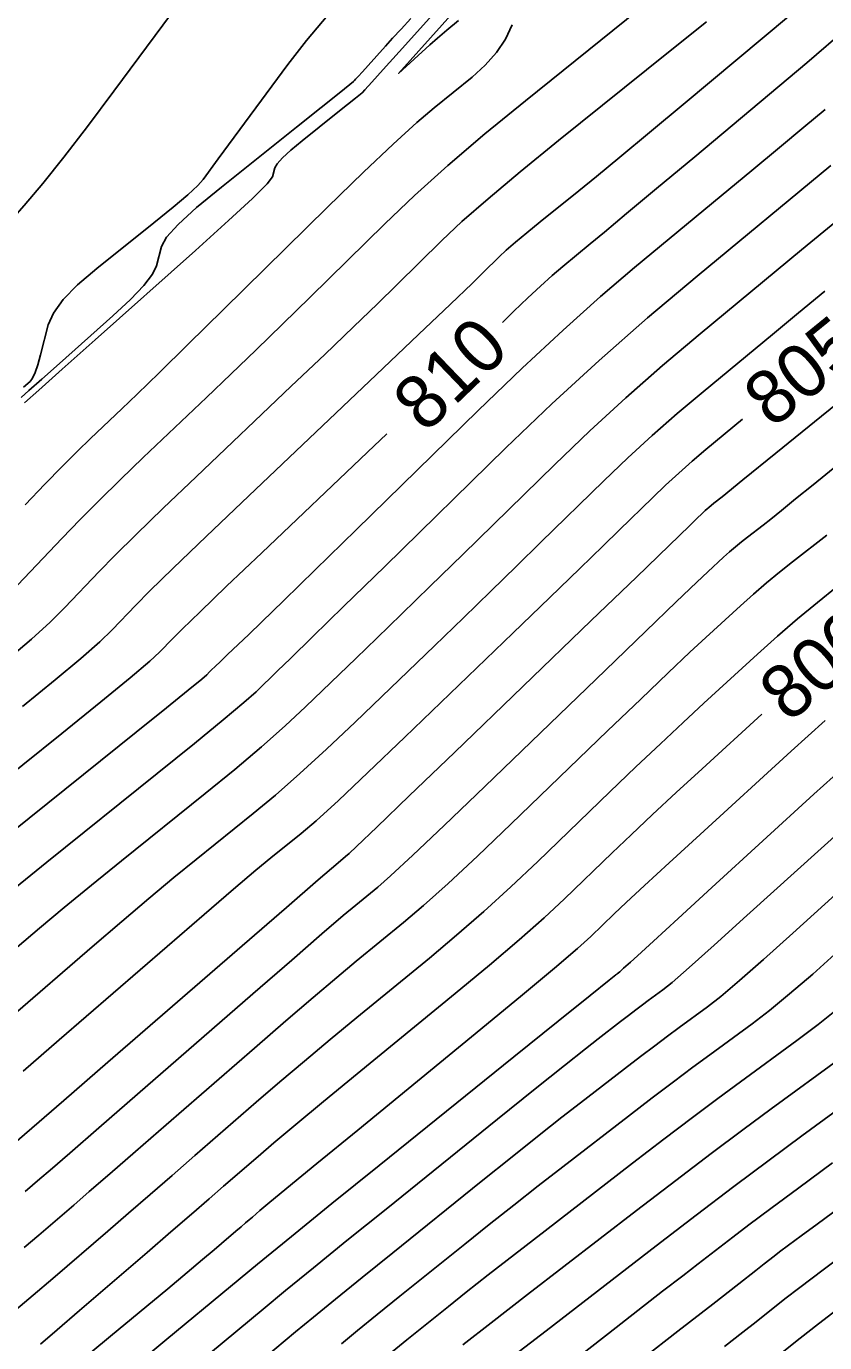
# Model space of a CAD drawing. Extents: x 2079879 to 2092887, y 778083 to 784051.
# Drawn here: x 2084061.2 to 2084103, y 780863.7 to 780932.5 of the extents above; entities that cross this region are included whole.
import ezdxf

# ---------------------------------------------------------------- set-up
doc = ezdxf.new("R2010")
doc.units = 0
doc.layers.add('DT_X_Contour_Major', color=7, linetype='Continuous')
doc.layers.add('DT_X_Contour_Minor', color=7, linetype='Continuous')

msp = doc.modelspace()

# ---------------------------------------------------------------- linework, layer by layer
at = {"layer": 'DT_X_Contour_Major'}
for points in [[(2084083.224, 780934.036), (2084080.694, 780931.221), (2084079.863, 780930.296), (2084079.268, 780929.633), (2084078.907, 780929.232), (2084078.782, 780929.094), (2084078.762, 780929.072), (2084078.671, 780928.998), (2084078.415, 780928.793), (2084077.992, 780928.455), (2084077.404, 780927.986), (2084075.614, 780926.559), (2084075.021, 780926.069), (2084074.586, 780925.67), (2084074.307, 780925.361), (2084074.185, 780925.144), (2084074.068, 780924.685), (2084073.784, 780924.315), (2084073.019, 780923.551), (2084071.772, 780922.392), (2084070.045, 780920.838), (2084064.797, 780916.168), (2084063.073, 780914.634), (2084061.837, 780913.535), (2084061.089, 780912.87)], [(2084104.171, 780932.492), (2084102.031, 780930.64), (2084096.158, 780925.736), (2084094.165, 780924.072), (2084092.588, 780922.757), (2084091.43, 780921.792), (2084090.688, 780921.177), (2084089.266, 780920.002), (2084088.706, 780919.525), (2084088.091, 780918.974), (2084087.421, 780918.35), (2084086.697, 780917.652), (2084086.101, 780917.07)], [(2084098.661, 780912.005), (2084096.748, 780910.424), (2084096.027, 780909.816), (2084095.324, 780909.197), (2084094.637, 780908.567), (2084093.967, 780907.927), (2084092.204, 780906.204), (2084091.361, 780905.384), (2084090.153, 780904.214), (2084088.58, 780902.696), (2084086.643, 780900.828), (2084080.991, 780895.382), (2084079.062, 780893.536), (2084077.515, 780892.081), (2084076.349, 780891.017), (2084075.565, 780890.346), (2084073.983, 780889.076), (2084073.199, 780888.43), (2084072.034, 780887.445), (2084070.487, 780886.12), (2084068.558, 780884.455), (2084062.906, 780879.563), (2084061.017, 780877.921)], [(2084080.05, 780911.243), (2084079.044, 780910.286), (2084073.516, 780905.034), (2084071.669, 780903.276), (2084070.277, 780901.943), (2084069.338, 780901.035), (2084068.852, 780900.551), (2084068.163, 780899.826), (2084067.649, 780899.357), (2084066.625, 780898.495), (2084065.09, 780897.24), (2084063.045, 780895.59), (2084056.91, 780890.667)], [(2084099.664, 780896.596), (2084096.539, 780893.736), (2084095.183, 780892.489), (2084093.946, 780891.341), (2084092.83, 780890.291), (2084091.834, 780889.34), (2084089.338, 780886.935), (2084088.279, 780885.949), (2084086.974, 780884.796), (2084085.422, 780883.475), (2084083.625, 780881.986), (2084078.503, 780877.792), (2084076.737, 780876.342), (2084075.284, 780875.139), (2084074.142, 780874.183), (2084073.312, 780873.474), (2084071.513, 780871.91), (2084070.757, 780871.255), (2084069.838, 780870.461), (2084068.756, 780869.528), (2084067.511, 780868.456), (2084063.974, 780865.414), (2084062.801, 780864.405), (2084061.933, 780863.66)], [(2084103.684, 780884.216), (2084102.33, 780883.007), (2084101.125, 780881.971), (2084100.07, 780881.105), (2084099.163, 780880.411), (2084096.944, 780878.789), (2084096.054, 780878.132), (2084095.05, 780877.379), (2084093.932, 780876.53), (2084092.7, 780875.584), (2084089.261, 780872.933), (2084087.973, 780871.935), (2084086.689, 780870.929), (2084085.409, 780869.915), (2084084.133, 780868.894), (2084080.735, 780866.16), (2084079.545, 780865.201), (2084078.524, 780864.374), (2084077.671, 780863.678)], [(2084105.037, 780871.756), (2084102.559, 780869.94), (2084101.721, 780869.325), (2084101.066, 780868.841), (2084100.595, 780868.488), (2084100.307, 780868.266), (2084099.784, 780867.849), (2084099.355, 780867.511), (2084098.46, 780866.813), (2084097.099, 780865.752), (2084095.273, 780864.33), (2084089.781, 780860.056), (2084087.717, 780858.447), (2084087.46, 780858.246)]]:
    msp.add_lwpolyline(points, dxfattribs=at)
at = {"layer": 'DT_X_Contour_Minor'}
for points in [[(2084086.912, 780937.046), (2084080.662, 780930.09), (2084082.293, 780931.578), (2084082.693, 780931.932), (2084083.195, 780932.356), (2084083.799, 780932.851)], [(2084069.632, 780934.388), (2084065.777, 780929.156), (2084064.399, 780927.312), (2084063.157, 780925.703), (2084062.051, 780924.328), (2084061.081, 780923.189), (2084058.675, 780920.464), (2084057.831, 780919.495), (2084057.106, 780918.631), (2084056.498, 780917.873), (2084056.009, 780917.22), (2084054.86, 780915.618), (2084054.221, 780914.817), (2084053.164, 780913.616), (2084051.69, 780912.016), (2084049.799, 780910.015), (2084044.2, 780904.145), (2084042.347, 780902.199), (2084040.988, 780900.762), (2084040.122, 780899.834), (2084039.75, 780899.415), (2084039.166, 780898.65), (2084027.781, 780889.557), (2084025.603, 780887.819)], [(2084093.215, 780933.405), (2084087.304, 780928.661), (2084085.182, 780926.925), (2084083.247, 780925.273), (2084081.501, 780923.707), (2084079.942, 780922.225), (2084076.036, 780918.388), (2084074.599, 780916.981), (2084073.218, 780915.639), (2084071.892, 780914.362), (2084070.621, 780913.149), (2084067.308, 780910.001), (2084066.111, 780908.852), (2084065.005, 780907.768), (2084063.99, 780906.749), (2084063.067, 780905.793), (2084060.725, 780903.332)], [(2084077.246, 780933.463), (2084075.851, 780931.816), (2084074.866, 780930.562), (2084071.23, 780925.628), (2084070.447, 780924.54), (2084070.16, 780924.224), (2084069.634, 780923.743), (2084068.87, 780923.096), (2084067.867, 780922.284), (2084064.874, 780919.898), (2084063.874, 780919.042), (2084063.117, 780918.264), (2084062.604, 780917.563), (2084062.334, 780916.941), (2084061.94, 780915.384), (2084061.794, 780914.858), (2084061.653, 780914.45), (2084061.516, 780914.159), (2084061.385, 780913.985), (2084061.039, 780913.678)], [(2084096.769, 780932.786), (2084094.791, 780931.196), (2084089.032, 780926.574), (2084087.031, 780924.948), (2084085.348, 780923.537), (2084083.983, 780922.341), (2084082.935, 780921.361), (2084080.566, 780919.033), (2084079.555, 780918.048), (2084078.299, 780916.837), (2084076.799, 780915.4), (2084075.054, 780913.739), (2084070.074, 780909.007), (2084068.355, 780907.366), (2084066.936, 780905.992), (2084065.816, 780904.885), (2084064.995, 780904.046), (2084063.204, 780902.163), (2084062.434, 780901.399), (2084061.465, 780900.517), (2084060.3, 780899.519)], [(2084081.312, 780932.954), (2084080.794, 780932.406), (2084080.348, 780931.926), (2084079.973, 780931.514), (2084079.068, 780930.507), (2084078.769, 780930.174), (2084078.551, 780929.931), (2084078.413, 780929.779), (2084078.356, 780929.716), (2084078.311, 780929.67), (2084078.112, 780929.507), (2084077.549, 780929.056), (2084076.622, 780928.315), (2084075.33, 780927.284), (2084071.399, 780924.149), (2084070.097, 780923.073), (2084069.14, 780922.197), (2084068.528, 780921.52), (2084068.259, 780921.042), (2084068.004, 780920.034), (2084067.789, 780919.587), (2084067.336, 780919.001), (2084066.644, 780918.276), (2084065.715, 780917.412), (2084062.918, 780914.923), (2084061.996, 780914.103), (2084061.328, 780913.509), (2084060.914, 780913.142)], [(2084101.066, 780933.066), (2084095.665, 780928.555), (2084093.798, 780926.999), (2084092.247, 780925.713), (2084091.013, 780924.698), (2084090.096, 780923.953), (2084088.071, 780922.329), (2084087.368, 780921.757), (2084086.777, 780921.261), (2084086.297, 780920.841), (2084085.929, 780920.497), (2084085.096, 780919.678), (2084084.511, 780919.114), (2084083.381, 780918.034), (2084081.706, 780916.439), (2084079.486, 780914.328), (2084072.839, 780908.013), (2084070.6, 780905.879), (2084068.868, 780904.216), (2084067.642, 780903.022), (2084066.924, 780902.298), (2084065.683, 780900.995), (2084065.041, 780900.378), (2084064.045, 780899.506), (2084062.695, 780898.379), (2084060.99, 780896.997)], [(2084086.611, 780932.627), (2084086.251, 780931.88), (2084085.781, 780931.175), (2084085.201, 780930.513), (2084084.51, 780929.893), (2084082.522, 780928.297), (2084081.614, 780927.522), (2084080.383, 780926.396), (2084078.828, 780924.919), (2084076.948, 780923.09), (2084071.506, 780917.743), (2084069.643, 780915.915), (2084068.136, 780914.442), (2084066.985, 780913.324), (2084066.189, 780912.559), (2084064.542, 780910.995), (2084063.866, 780910.339), (2084063.074, 780909.545), (2084062.164, 780908.612), (2084061.138, 780907.541)], [(2084102.977, 780928.2), (2084101.87, 780927.277), (2084100.594, 780926.217), (2084099.15, 780925.02), (2084097.537, 780923.686), (2084093.012, 780919.946), (2084091.228, 780918.426), (2084089.27, 780916.673), (2084087.138, 780914.686), (2084084.833, 780912.465), (2084078.452, 780906.231), (2084076.306, 780904.136), (2084074.654, 780902.526), (2084073.496, 780901.402), (2084072.832, 780900.763), (2084071.72, 780899.706), (2084071.348, 780899.352), (2084071.068, 780899.084), (2084070.879, 780898.901), (2084070.781, 780898.803), (2084070.642, 780898.657), (2084070.371, 780898.429), (2084069.663, 780897.852), (2084068.516, 780896.927), (2084066.932, 780895.654), (2084060.442, 780890.447)], [(2084103.28, 780925.281), (2084096.283, 780919.497), (2084093.69, 780917.309), (2084091.159, 780915.083), (2084088.689, 780912.817), (2084086.28, 780910.513), (2084079.938, 780904.317), (2084077.804, 780902.233), (2084076.159, 780900.628), (2084075.003, 780899.502), (2084074.336, 780898.855), (2084073.208, 780897.768), (2084072.567, 780897.195), (2084071.492, 780896.289), (2084069.982, 780895.051), (2084068.037, 780893.482), (2084062.27, 780888.854), (2084060.306, 780887.273)], [(2084103.587, 780922.381), (2084101.751, 780920.864), (2084096.438, 780916.473), (2084094.469, 780914.812), (2084092.547, 780913.121), (2084090.671, 780911.4), (2084088.842, 780909.651), (2084084.027, 780904.946), (2084082.323, 780903.283), (2084080.824, 780901.824), (2084079.529, 780900.567), (2084078.438, 780899.513), (2084075.802, 780896.973), (2084074.732, 780895.975), (2084073.499, 780894.886), (2084072.104, 780893.707), (2084070.546, 780892.437), (2084066.174, 780888.928), (2084064.603, 780887.659), (2084063.17, 780886.483), (2084061.873, 780885.399), (2084060.714, 780884.408)], [(2084102.964, 780918.702), (2084101.588, 780917.574), (2084100.222, 780916.448), (2084096.593, 780913.449), (2084095.248, 780912.314), (2084093.935, 780911.159), (2084092.654, 780909.984), (2084091.405, 780908.789), (2084088.116, 780905.575), (2084086.842, 780904.334), (2084085.488, 780903.019), (2084084.055, 780901.631), (2084082.541, 780900.17), (2084078.396, 780896.177), (2084076.897, 780894.755), (2084075.507, 780893.484), (2084074.227, 780892.362), (2084073.056, 780891.391), (2084070.079, 780889.002), (2084068.901, 780888.045), (2084067.602, 780886.964), (2084066.18, 780885.759), (2084064.636, 780884.432), (2084060.356, 780880.727)], [(2084110.041, 780918.034), (2084102.795, 780912.173), (2084100.405, 780910.24), (2084098.67, 780908.836), (2084097.589, 780907.961), (2084097.164, 780907.616), (2084096.903, 780907.4), (2084096.806, 780907.318), (2084096.712, 780907.235), (2084096.62, 780907.151), (2084096.53, 780907.065), (2084096.293, 780906.833), (2084095.88, 780906.434), (2084094.818, 780905.41), (2084093.106, 780903.76), (2084090.746, 780901.486), (2084083.585, 780894.587), (2084081.227, 780892.316), (2084079.522, 780890.678), (2084078.472, 780889.673), (2084078.075, 780889.3), (2084077.888, 780889.15), (2084077.497, 780888.816), (2084076.466, 780887.926), (2084074.793, 780886.48), (2084072.48, 780884.478), (2084065.457, 780878.4), (2084063.145, 780876.397), (2084061.477, 780874.949), (2084060.453, 780874.054)], [(2084104.997, 780910.74), (2084102.347, 780908.58), (2084101.438, 780907.841), (2084100.701, 780907.245), (2084100.135, 780906.791), (2084099.74, 780906.48), (2084098.914, 780905.84), (2084098.604, 780905.595), (2084098.294, 780905.338), (2084097.983, 780905.07), (2084097.672, 780904.791), (2084096.842, 780904.031), (2084096.273, 780903.497), (2084095.191, 780902.464), (2084093.595, 780900.931), (2084091.485, 780898.9), (2084085.173, 780892.819), (2084083.048, 780890.779), (2084081.408, 780889.222), (2084080.251, 780888.146), (2084079.579, 780887.553), (2084078.431, 780886.613), (2084077.772, 780886.059), (2084076.654, 780885.101), (2084075.077, 780883.739), (2084073.042, 780881.973), (2084067.004, 780876.726), (2084064.986, 780874.973), (2084063.462, 780873.65), (2084062.433, 780872.757), (2084061.897, 780872.293), (2084061.126, 780871.631)], [(2084103.068, 780905.946), (2084101.265, 780904.55), (2084100.589, 780904.014), (2084099.911, 780903.454), (2084099.233, 780902.868), (2084098.554, 780902.259), (2084096.741, 780900.6), (2084095.91, 780899.828), (2084094.776, 780898.756), (2084093.34, 780897.384), (2084091.601, 780895.713), (2084086.562, 780890.857), (2084084.792, 780889.169), (2084083.263, 780887.746), (2084081.975, 780886.589), (2084080.928, 780885.697), (2084078.455, 780883.673), (2084077.427, 780882.82), (2084076.197, 780881.781), (2084074.765, 780880.554), (2084073.132, 780879.14), (2084068.507, 780875.121), (2084066.903, 780873.729), (2084065.563, 780872.566), (2084064.486, 780871.634), (2084063.671, 780870.931), (2084061.85, 780869.364), (2084061.083, 780868.712)], [(2084103.617, 780903.259), (2084102.574, 780902.433), (2084101.529, 780901.569), (2084100.483, 780900.666), (2084099.435, 780899.726), (2084096.64, 780897.168), (2084095.546, 780896.158), (2084094.361, 780895.048), (2084093.085, 780893.838), (2084091.718, 780892.526), (2084087.95, 780888.896), (2084086.536, 780887.559), (2084085.119, 780886.271), (2084083.699, 780885.032), (2084082.276, 780883.842), (2084078.479, 780880.732), (2084077.082, 780879.581), (2084075.741, 780878.46), (2084074.454, 780877.369), (2084073.222, 780876.307), (2084070.01, 780873.516), (2084068.821, 780872.484), (2084067.664, 780871.482), (2084066.539, 780870.511), (2084065.446, 780869.569), (2084062.574, 780867.098), (2084061.551, 780866.222), (2084060.637, 780865.446)], [(2084102.983, 780896.262), (2084101.199, 780894.661), (2084096.438, 780890.304), (2084094.819, 780888.82), (2084093.531, 780887.633), (2084092.575, 780886.744), (2084091.95, 780886.153), (2084090.726, 780884.974), (2084090.023, 780884.339), (2084088.829, 780883.321), (2084087.146, 780881.918), (2084084.973, 780880.13), (2084078.526, 780874.851), (2084076.393, 780873.103), (2084074.827, 780871.819), (2084073.83, 780870.998), (2084073.401, 780870.64), (2084073.016, 780870.305), (2084072.854, 780870.165), (2084072.656, 780869.994), (2084072.424, 780869.794), (2084072.157, 780869.564), (2084071.399, 780868.912), (2084071.01, 780868.581), (2084070.411, 780868.079), (2084069.603, 780867.405), (2084068.585, 780866.558), (2084065.591, 780864.073), (2084064.57, 780863.225)], [(2084104.407, 780894.22), (2084102.39, 780892.412), (2084097.059, 780887.533), (2084095.293, 780885.918), (2084093.994, 780884.729), (2084093.161, 780883.967), (2084092.794, 780883.633), (2084092.439, 780883.311), (2084092.32, 780883.204), (2084092.233, 780883.125), (2084092.177, 780883.075), (2084092.151, 780883.054), (2084092.123, 780883.033), (2084092.112, 780883.025), (2084092.099, 780883.016), (2084092.085, 780883.005), (2084092.07, 780882.993), (2084092.027, 780882.96), (2084091.682, 780882.683), (2084090.68, 780881.877), (2084089.02, 780880.542), (2084086.703, 780878.678), (2084079.647, 780873.001), (2084077.176, 780871.01), (2084075.055, 780869.292), (2084073.285, 780867.847), (2084071.865, 780866.677), (2084068.546, 780863.921), (2084067.382, 780862.956)], [(2084104.005, 780890.693), (2084098.892, 780886.062), (2084097.178, 780884.516), (2084095.873, 780883.353), (2084094.977, 780882.572), (2084094.488, 780882.173), (2084093.73, 780881.618), (2084093.426, 780881.394), (2084093.083, 780881.137), (2084092.701, 780880.847), (2084092.28, 780880.523), (2084091.105, 780879.618), (2084090.446, 780879.1), (2084089.35, 780878.228), (2084087.816, 780877), (2084085.846, 780875.417), (2084080.009, 780870.721), (2084077.965, 780869.073), (2084076.211, 780867.652), (2084074.747, 780866.458), (2084073.573, 780865.49), (2084070.827, 780863.21)], [(2084105.749, 780889.18), (2084101.288, 780885.139), (2084099.754, 780883.762), (2084098.499, 780882.662), (2084097.523, 780881.838), (2084096.826, 780881.292), (2084095.337, 780880.204), (2084094.74, 780879.763), (2084094.067, 780879.258), (2084093.317, 780878.688), (2084092.49, 780878.054), (2084090.183, 780876.275), (2084089.21, 780875.517), (2084088.02, 780874.578), (2084086.613, 780873.458), (2084084.99, 780872.155), (2084080.372, 780868.441), (2084078.755, 780867.137), (2084077.368, 780866.013), (2084076.209, 780865.068), (2084075.28, 780864.302), (2084073.108, 780862.499)], [(2084103.751, 780881.279), (2084102.616, 780880.372), (2084101.5, 780879.53), (2084098.55, 780877.374), (2084097.368, 780876.501), (2084096.034, 780875.5), (2084094.548, 780874.371), (2084092.91, 780873.114), (2084088.339, 780869.59), (2084086.737, 780868.352), (2084085.359, 780867.28), (2084084.206, 780866.373), (2084083.277, 780865.633), (2084081.098, 780863.88), (2084080.335, 780863.265)], [(2084103.838, 780878.65), (2084100.157, 780875.959), (2084098.682, 780874.87), (2084097.018, 780873.621), (2084095.164, 780872.213), (2084093.12, 780870.644), (2084087.417, 780866.248), (2084085.501, 780864.769), (2084084.029, 780863.63)], [(2084106.175, 780877.769), (2084101.764, 780874.544), (2084100.047, 780873.278), (2084098.204, 780871.899), (2084096.235, 780870.405), (2084094.139, 780868.799), (2084088.384, 780864.362), (2084086.459, 780862.878)], [(2084103.371, 780873.129), (2084101.599, 780871.831), (2084100.138, 780870.753), (2084098.989, 780869.895), (2084098.151, 780869.259), (2084096.332, 780867.857), (2084095.528, 780867.235), (2084094.478, 780866.422), (2084093.184, 780865.417), (2084091.646, 780864.22), (2084087.215, 780860.772)], [(2084104.531, 780868.773), (2084102.872, 780867.544), (2084101.652, 780866.628), (2084100.871, 780866.024), (2084099.374, 780864.831), (2084098.68, 780864.282), (2084097.721, 780863.529)], [(2084103.775, 780865.586), (2084102.483, 780864.602), (2084101.434, 780863.782), (2084098.965, 780861.814)]]:
    msp.add_lwpolyline(points, dxfattribs=at)

# ---------------------------------------------------------------- texts
at = {"layer": 'DT_X_Contour_Major'}
for s, rotation, p in [('810', 43.91547, (2084082.074, 780911.225)), ('805', 39.10593, (2084100.223, 780911.481)), ('800', 40.40348, (2084101.091, 780896.092))]:
    msp.add_text(s, height=2.8, rotation=rotation, dxfattribs=at).set_placement(p)

doc.saveas('drawing.dxf')
